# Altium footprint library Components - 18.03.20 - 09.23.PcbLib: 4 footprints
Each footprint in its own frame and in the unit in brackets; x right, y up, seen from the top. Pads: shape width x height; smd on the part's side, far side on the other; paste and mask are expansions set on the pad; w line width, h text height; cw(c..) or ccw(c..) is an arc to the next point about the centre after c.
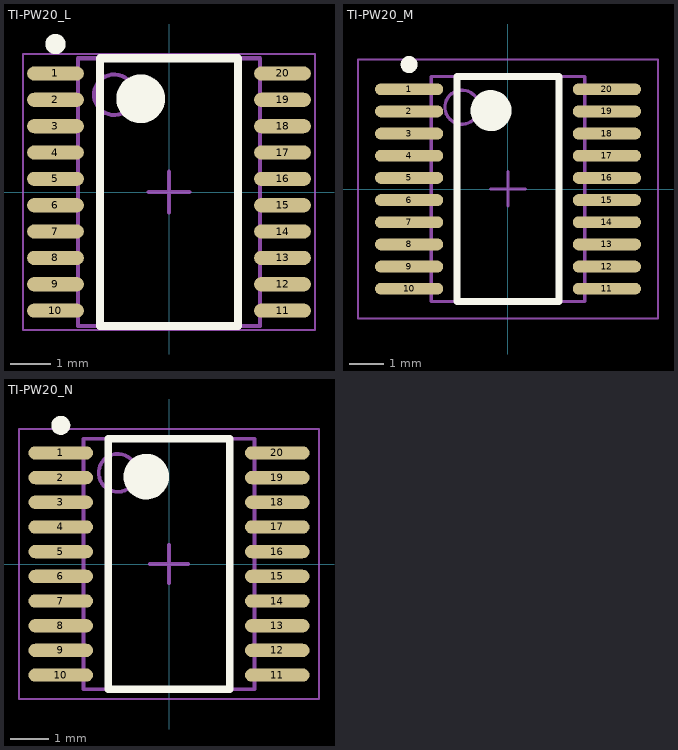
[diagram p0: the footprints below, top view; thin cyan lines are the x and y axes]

## PCBComponent_1 [mm]

## TI-PW20_L [mm] "SOP, 20-Leads, Body 6.5x4.4mm, Pitch 0.65mm, IPC High Density"
height 1.2
pads (20):
  oval 1.4x0.35 smd: 1(-2.8,2.925) 2(-2.8,2.275) 3(-2.8,1.625) 4(-2.8,0.975) 5(-2.8,0.325) 6(-2.8,-0.325) 7(-2.8,-0.975) 8(-2.8,-1.625) 9(-2.8,-2.275) 10(-2.8,-2.925) 11(2.8,-2.925) 12(2.8,-2.275) 13(2.8,-1.625) 14(2.8,-0.975) 15(2.8,-0.325) 16(2.8,0.325) 17(2.8,0.975) 18(2.8,1.625) 19(2.8,2.275) 20(2.8,2.925)
Top Overlay:
  circle w0.25: c-2.8,3.65 r0.125
  circle w0.6: c-0.7,2.3 r0.3
  lines w0.2: -1.7,-3.3 -1.7,3.3 1.7,3.3 1.7,-3.3 -1.7,-3.3
Mechanical 13:
  circle w0.1: c-1.35,2.4 r0.5
  lines w0.1: -2.25,-3.3 -2.25,3.3 2.25,3.3 2.25,-3.3 -2.25,-3.3
Mechanical 15:
  lines w0.05: -3.6,-3.4 -3.6,3.4 3.6,3.4 3.6,-3.4 -3.6,-3.4
  lines w0.1: -0.5,0 0.5,0 ; 0,-0.5 0,0.5
3D body: height 1.2, standoff 0.05, extent -2.25,-3.3 2.25,3.3

## TI-PW20_M [mm] "SOP, 20-Leads, Body 6.5x4.4mm, Pitch 0.65mm, IPC Low Density"
height 1.2
pads (20):
  oval 2x0.35 smd: 1(-2.9,2.925) 2(-2.9,2.275) 3(-2.9,1.625) 4(-2.9,0.975) 5(-2.9,0.325) 6(-2.9,-0.325) 7(-2.9,-0.975) 8(-2.9,-1.625) 9(-2.9,-2.275) 10(-2.9,-2.925) 11(2.9,-2.925) 12(2.9,-2.275) 13(2.9,-1.625) 14(2.9,-0.975) 15(2.9,-0.325) 16(2.9,0.325) 17(2.9,0.975) 18(2.9,1.625) 19(2.9,2.275) 20(2.9,2.925)
Top Overlay:
  circle w0.6: c-0.5,2.3 r0.3
  circle w0.25: c-2.9,3.65 r0.125
  lines w0.2: -1.5,-3.3 1.5,-3.3 1.5,3.3 -1.5,3.3 -1.5,-3.3
Mechanical 13:
  circle w0.1: c-1.35,2.4 r0.5
  lines w0.1: -2.25,-3.3 2.25,-3.3 2.25,3.3 -2.25,3.3 -2.25,-3.3
Mechanical 15:
  lines w0.05: -4.4,-3.8 4.4,-3.8 4.4,3.8 -4.4,3.8 -4.4,-3.8
  lines w0.1: -0.5,0 0.5,0 ; 0,-0.5 0,0.5
3D body: height 1.2, standoff 0.05, extent -2.25,-3.3 2.25,3.3

## TI-PW20_N [mm] "SOP, 20-Leads, Body 6.5x4.4mm, Pitch 0.65mm, IPC Medium Density"
height 1.2
pads (20):
  oval 1.7x0.35 smd: 1(-2.85,2.925) 2(-2.85,2.275) 3(-2.85,1.625) 4(-2.85,0.975) 5(-2.85,0.325) 6(-2.85,-0.325) 7(-2.85,-0.975) 8(-2.85,-1.625) 9(-2.85,-2.275) 10(-2.85,-2.925) 11(2.85,-2.925) 12(2.85,-2.275) 13(2.85,-1.625) 14(2.85,-0.975) 15(2.85,-0.325) 16(2.85,0.325) 17(2.85,0.975) 18(2.85,1.625) 19(2.85,2.275) 20(2.85,2.925)
Top Overlay:
  circle w0.25: c-2.85,3.65 r0.125
  circle w0.6: c-0.6,2.3 r0.3
  lines w0.2: -1.6,-3.3 -1.6,3.3 1.6,3.3 1.6,-3.3 -1.6,-3.3
Mechanical 13:
  circle w0.1: c-1.35,2.4 r0.5
  lines w0.1: -2.25,-3.3 -2.25,3.3 2.25,3.3 2.25,-3.3 -2.25,-3.3
Mechanical 15:
  lines w0.05: -3.95,-3.55 -3.95,3.55 3.95,3.55 3.95,-3.55 -3.95,-3.55
  lines w0.1: -0.5,0 0.5,0 ; 0,-0.5 0,0.5
3D body: height 1.2, standoff 0.05, extent -2.25,-3.3 2.25,3.3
